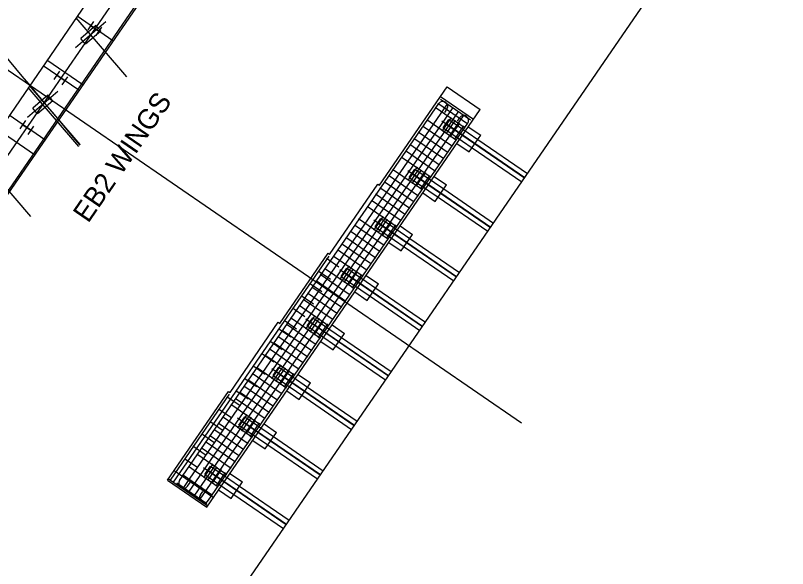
# Model space of a CAD drawing. Extents: x 2378999 to 2381348, y 331302 to 333122.
# Drawn here: x 2379522.9 to 2379599.9, y 331848.3 to 331903.6 of the extents above; entities that cross this region are included whole.
import ezdxf

# ---------------------------------------------------------------- set-up
doc = ezdxf.new("R2010")
doc.units = 0
for name, color, linetype in [('Arrowhead Terminators', 7, 'Continuous'), ('Dimension Lines', 7, 'Continuous'), ('Dimension Lines CELL', 7, 'Continuous'), ('Mis Work Point CELL', 7, 'Continuous'), ('P_SMU_Bent_Cap', 7, 'Continuous'), ('P_SMU_D_Deck_Outline', 7, 'Continuous'), ('P_SMU_Girder_Concrete', 7, 'Continuous'), ('P_SMU_Mis_L_Lines', 7, 'Continuous'), ('P_SMU_Mis_Long_Chord', 7, 'Continuous'), ('P_SMU_Rebar_B_Bar', 7, 'Continuous'), ('P_SMU_Rebar_U_Bar', 7, 'Continuous'), ('Plan Sheet CELL', 7, 'Continuous'), ('Rebar Lines', 7, 'Continuous'), ('Scratch_Level_0', 7, 'Continuous'), ('Sup Concrete Slab Lines', 7, 'Continuous')]:
    doc.layers.add(name, color=color, linetype=linetype)

msp = doc.modelspace()

# ---------------------------------------------------------------- linework, layer by layer
at = {"layer": 'Arrowhead Terminators'}
for p, q in [((2379539.258, 331857.115), (2379565.129, 331894.772)), ((2379539.599, 331856.287), (2379566.025, 331894.75)), ((2379540.148, 331855.909), (2379566.574, 331894.373)), ((2379540.698, 331855.532), (2379567.124, 331893.995)), ((2379565.936, 331894.217), (2379565.7, 331893.874)), ((2379541.247, 331855.154), (2379567.673, 331893.618)), ((2379567.207, 331893.344), (2379566.971, 331893.001)), ((2379542.142, 331855.133), (2379568.014, 331892.79)), ((2379538.663, 331856.93), (2379554.188, 331879.527)), ((2379538.346, 331857.148), (2379544.245, 331865.733)), ((2379540.065, 331856.561), (2379540.301, 331856.904)), ((2379541.335, 331855.688), (2379541.571, 331856.031))]:
    msp.add_line(p, q, dxfattribs=at)
for centre, start, end in [((2379565.533, 331894.494), 325.50932, 145.50932), ((2379567.611, 331893.067), 325.50932, 145.50932), ((2379539.661, 331856.838), 145.50932, 325.50932), ((2379541.739, 331855.41), 145.50932, 325.50932)]:
    msp.add_arc(centre, 0.49, start, end, dxfattribs=at)
at = {"layer": 'Dimension Lines'}
for p, q in [((2379565.04, 331894.789), (2379568.028, 331892.737)), ((2379565.311, 331895.183), (2379568.299, 331893.13)), ((2379564.77, 331894.396), (2379567.758, 331892.343)), ((2379563.921, 331893.159), (2379566.908, 331891.107)), ((2379565.453, 331892.005), (2379566.397, 331893.379)), ((2379565.865, 331891.722), (2379566.809, 331893.096)), ((2379563.496, 331892.541), (2379566.484, 331890.488)), ((2379566.277, 331891.439), (2379567.221, 331892.813)), ((2379566.689, 331891.156), (2379567.633, 331892.53)), ((2379563.071, 331891.923), (2379566.059, 331889.87)), ((2379562.646, 331891.305), (2379565.634, 331889.252)), ((2379561.797, 331890.069), (2379564.785, 331888.016)), ((2379562.222, 331890.687), (2379565.21, 331888.634)), ((2379561.372, 331889.45), (2379564.36, 331887.398)), ((2379562.056, 331887.06), (2379562.999, 331888.434)), ((2379560.523, 331888.214), (2379563.511, 331886.161)), ((2379562.468, 331886.777), (2379563.411, 331888.151)), ((2379562.88, 331886.494), (2379563.824, 331887.867)), ((2379559.674, 331886.978), (2379562.661, 331884.925)), ((2379560.098, 331887.596), (2379563.086, 331885.543)), ((2379563.292, 331886.211), (2379564.236, 331887.584)), ((2379559.249, 331886.36), (2379562.237, 331884.307)), ((2379558.824, 331885.741), (2379561.812, 331883.689)), ((2379558.399, 331885.123), (2379561.387, 331883.071)), ((2379557.975, 331884.505), (2379560.963, 331882.452)), ((2379557.125, 331883.269), (2379560.113, 331881.216)), ((2379558.658, 331882.115), (2379559.602, 331883.488)), ((2379559.07, 331881.832), (2379560.014, 331883.205)), ((2379556.701, 331882.651), (2379559.688, 331880.598)), ((2379559.482, 331881.548), (2379560.426, 331882.922)), ((2379559.894, 331881.265), (2379560.838, 331882.639)), ((2379556.276, 331882.032), (2379559.264, 331879.98)), ((2379555.426, 331880.796), (2379558.414, 331878.743)), ((2379555.851, 331881.414), (2379558.839, 331879.362)), ((2379555.002, 331880.178), (2379557.99, 331878.125)), ((2379554.577, 331879.56), (2379557.565, 331877.507)), ((2379555.26, 331877.169), (2379556.204, 331878.543)), ((2379553.303, 331877.705), (2379556.291, 331875.653)), ((2379553.728, 331878.323), (2379556.715, 331876.271)), ((2379555.672, 331876.886), (2379556.616, 331878.26)), ((2379556.084, 331876.603), (2379557.028, 331877.977)), ((2379556.497, 331876.32), (2379557.44, 331877.694)), ((2379552.878, 331877.087), (2379555.866, 331875.034)), ((2379552.454, 331876.469), (2379555.441, 331874.416)), ((2379552.029, 331875.851), (2379555.017, 331873.798)), ((2379551.179, 331874.614), (2379554.167, 331872.562)), ((2379551.604, 331875.233), (2379554.592, 331873.18)), ((2379550.33, 331873.378), (2379553.318, 331871.325)), ((2379551.863, 331872.224), (2379552.806, 331873.598)), ((2379552.275, 331871.941), (2379553.219, 331873.315)), ((2379552.687, 331871.658), (2379553.631, 331873.032)), ((2379549.905, 331872.76), (2379552.893, 331870.707)), ((2379553.099, 331871.375), (2379554.043, 331872.748)), ((2379549.056, 331871.524), (2379552.044, 331869.471)), ((2379549.481, 331872.142), (2379552.468, 331870.089)), ((2379548.631, 331870.905), (2379551.619, 331868.853)), ((2379548.207, 331870.287), (2379551.194, 331868.235)), ((2379547.782, 331869.669), (2379550.77, 331867.616)), ((2379546.932, 331868.433), (2379549.92, 331866.38)), ((2379548.465, 331867.279), (2379549.409, 331868.652)), ((2379546.508, 331867.815), (2379549.496, 331865.762)), ((2379548.877, 331866.996), (2379549.821, 331868.369)), ((2379549.289, 331866.713), (2379550.233, 331868.086)), ((2379549.701, 331866.429), (2379550.645, 331867.803)), ((2379546.083, 331867.197), (2379549.071, 331865.144)), ((2379545.658, 331866.578), (2379548.646, 331864.526)), ((2379544.809, 331865.342), (2379547.797, 331863.289)), ((2379545.234, 331865.96), (2379548.221, 331863.907)), ((2379544.384, 331864.724), (2379547.372, 331862.671)), ((2379543.535, 331863.488), (2379546.523, 331861.435)), ((2379545.067, 331862.333), (2379546.011, 331863.707)), ((2379545.479, 331862.05), (2379546.423, 331863.424)), ((2379545.892, 331861.767), (2379546.835, 331863.141)), ((2379542.685, 331862.251), (2379545.673, 331860.198)), ((2379543.11, 331862.869), (2379546.098, 331860.817)), ((2379546.304, 331861.484), (2379547.247, 331862.858)), ((2379542.261, 331861.633), (2379545.248, 331859.58)), ((2379541.836, 331861.015), (2379544.824, 331858.962)), ((2379541.411, 331860.397), (2379544.399, 331858.344)), ((2379540.987, 331859.779), (2379543.974, 331857.726)), ((2379540.137, 331858.542), (2379543.125, 331856.489)), ((2379541.67, 331857.388), (2379542.614, 331858.762)), ((2379542.082, 331857.105), (2379543.026, 331858.479)), ((2379539.563, 331857.707), (2379542.551, 331855.654)), ((2379542.494, 331856.822), (2379543.438, 331858.196)), ((2379542.906, 331856.539), (2379543.85, 331857.912)), ((2379538.989, 331856.871), (2379541.977, 331854.819))]:
    msp.add_line(p, q, dxfattribs=at)
at = {"layer": 'Dimension Lines CELL'}
msp.add_line((2379573.397, 331862.836), (2379390.08, 331988.783), dxfattribs=at)
at = {"layer": 'Mis Work Point CELL'}
for p, q in [((2379526.805, 331819.101), (2379599.933, 331925.541)), ((2379512.42, 331875.462), (2379539.034, 331914.2))]:
    msp.add_line(p, q, dxfattribs=at)
at = {"layer": 'P_SMU_Bent_Cap'}
for p, q in [((2379531.913, 331902.921), (2379528.872, 331900.323)), ((2379527.125, 331895.952), (2379524.084, 331893.354))]:
    msp.add_line(p, q, dxfattribs=at)
at = {"layer": 'P_SMU_D_Deck_Outline'}
for p, q in [((2379530.909, 331902.557), (2379529.388, 331901.257)), ((2379531.396, 331901.986), (2379530.909, 331902.557)), ((2379531.396, 331901.986), (2379529.876, 331900.687)), ((2379529.876, 331900.687), (2379529.388, 331901.257)), ((2379526.121, 331895.588), (2379524.601, 331894.289)), ((2379526.609, 331895.018), (2379526.121, 331895.588)), ((2379526.609, 331895.018), (2379525.088, 331893.719)), ((2379525.088, 331893.719), (2379524.601, 331894.289))]:
    msp.add_line(p, q, dxfattribs=at)
at = {"layer": 'P_SMU_Girder_Concrete'}
for p, q in [((2379530.135, 331902.116), (2379530.701, 331902.94)), ((2379530.418, 331902.528), (2379531.229, 331901.971)), ((2379530.945, 331901.559), (2379531.512, 331902.383)), ((2379526.737, 331897.17), (2379527.304, 331897.994)), ((2379527.021, 331897.582), (2379527.831, 331897.026)), ((2379527.548, 331896.613), (2379528.114, 331897.438)), ((2379523.34, 331892.225), (2379523.906, 331893.049)), ((2379565.573, 331892.327), (2379566.139, 331893.151)), ((2379566.139, 331893.151), (2379569.024, 331891.17)), ((2379523.623, 331892.637), (2379524.433, 331892.08)), ((2379524.15, 331891.668), (2379524.716, 331892.492)), ((2379565.573, 331892.327), (2379568.458, 331890.345)), ((2379565.846, 331892.724), (2379573.686, 331887.338)), ((2379565.867, 331892.754), (2379573.707, 331887.368)), ((2379569.024, 331891.17), (2379573.979, 331887.765)), ((2379568.458, 331890.345), (2379573.413, 331886.941)), ((2379562.176, 331887.382), (2379562.742, 331888.206)), ((2379562.448, 331887.779), (2379570.288, 331882.393)), ((2379562.469, 331887.809), (2379570.309, 331882.423)), ((2379562.742, 331888.206), (2379565.627, 331886.224)), ((2379562.176, 331887.382), (2379565.06, 331885.4)), ((2379565.627, 331886.224), (2379570.582, 331882.82)), ((2379565.06, 331885.4), (2379570.016, 331881.996)), ((2379558.778, 331882.437), (2379559.344, 331883.261)), ((2379559.344, 331883.261), (2379562.229, 331881.279)), ((2379558.778, 331882.437), (2379561.663, 331880.455)), ((2379559.051, 331882.834), (2379566.891, 331877.447)), ((2379559.071, 331882.864), (2379566.911, 331877.477)), ((2379562.229, 331881.279), (2379567.184, 331877.874)), ((2379561.663, 331880.455), (2379566.618, 331877.05)), ((2379555.38, 331877.491), (2379555.947, 331878.316)), ((2379555.653, 331877.889), (2379563.493, 331872.502)), ((2379555.674, 331877.918), (2379563.514, 331872.532)), ((2379555.947, 331878.316), (2379558.831, 331876.334)), ((2379555.38, 331877.491), (2379558.265, 331875.509)), ((2379558.831, 331876.334), (2379563.787, 331872.929)), ((2379558.265, 331875.509), (2379563.22, 331872.105)), ((2379551.983, 331872.546), (2379552.549, 331873.37)), ((2379552.549, 331873.37), (2379555.434, 331871.388)), ((2379551.983, 331872.546), (2379554.867, 331870.564)), ((2379552.256, 331872.943), (2379560.096, 331867.557)), ((2379552.276, 331872.973), (2379560.116, 331867.587)), ((2379555.434, 331871.388), (2379560.389, 331867.984)), ((2379554.867, 331870.564), (2379559.823, 331867.16)), ((2379548.585, 331867.601), (2379549.151, 331868.425)), ((2379549.151, 331868.425), (2379552.036, 331866.443)), ((2379548.858, 331867.998), (2379556.698, 331862.612)), ((2379548.878, 331868.028), (2379556.718, 331862.641)), ((2379548.585, 331867.601), (2379551.47, 331865.619)), ((2379552.036, 331866.443), (2379556.991, 331863.039)), ((2379551.47, 331865.619), (2379556.425, 331862.214)), ((2379545.187, 331862.655), (2379545.754, 331863.48)), ((2379545.46, 331863.053), (2379553.3, 331857.666)), ((2379545.481, 331863.082), (2379553.321, 331857.696)), ((2379545.754, 331863.48), (2379548.638, 331861.498)), ((2379545.187, 331862.655), (2379548.072, 331860.673)), ((2379548.638, 331861.498), (2379553.594, 331858.093)), ((2379548.072, 331860.673), (2379553.027, 331857.269)), ((2379541.79, 331857.71), (2379542.356, 331858.534)), ((2379542.356, 331858.534), (2379545.241, 331856.552)), ((2379541.79, 331857.71), (2379544.675, 331855.728)), ((2379542.063, 331858.107), (2379549.903, 331852.721)), ((2379542.083, 331858.137), (2379549.923, 331852.751)), ((2379545.241, 331856.552), (2379550.196, 331853.148)), ((2379544.675, 331855.728), (2379549.63, 331852.324))]:
    msp.add_line(p, q, dxfattribs=at)
at = {"layer": 'P_SMU_Mis_L_Lines'}
for p, q in [((2379533.98, 331897.423), (2379528.935, 331903.327)), ((2379529.192, 331890.454), (2379524.148, 331896.359)), ((2379524.404, 331883.486), (2379519.36, 331889.39))]:
    msp.add_line(p, q, dxfattribs=at)
at = {"layer": 'P_SMU_Mis_Long_Chord'}
msp.add_arc((2384957.239, 336436.342), 7080, 219.8160166, 219.9451668, dxfattribs=at)
at = {"layer": 'P_SMU_Rebar_B_Bar'}
for p, q in [((2379536.991, 331915.053), (2379511.549, 331878.021)), ((2379540.491, 331912.495), (2379513.877, 331873.757)), ((2379529.591, 331896.629), (2379526.019, 331899.083)), ((2379559.207, 331886.594), (2379565.952, 331896.411)), ((2379565.952, 331896.411), (2379569.249, 331894.146)), ((2379565.295, 331895.454), (2379568.592, 331893.189)), ((2379541.977, 331854.451), (2379569.249, 331894.146)), ((2379568.071, 331892.431), (2379569.307, 331891.582)), ((2379524.777, 331889.623), (2379521.206, 331892.077)), ((2379568.175, 331889.933), (2379569.307, 331891.582)), ((2379566.939, 331890.783), (2379568.175, 331889.933)), ((2379564.673, 331887.486), (2379565.91, 331886.636)), ((2379554.235, 331879.697), (2379559.048, 331886.703)), ((2379559.048, 331886.703), (2379559.207, 331886.594)), ((2379564.777, 331884.988), (2379565.91, 331886.636)), ((2379563.541, 331885.837), (2379564.777, 331884.988)), ((2379561.276, 331882.54), (2379562.512, 331881.691)), ((2379561.38, 331880.043), (2379562.512, 331881.691)), ((2379560.143, 331880.892), (2379561.38, 331880.043)), ((2379549.263, 331872.8), (2379554.077, 331879.806)), ((2379554.077, 331879.806), (2379554.235, 331879.697)), ((2379557.878, 331877.595), (2379559.114, 331876.746)), ((2379557.982, 331875.097), (2379559.114, 331876.746)), ((2379556.746, 331875.947), (2379557.982, 331875.097)), ((2379544.291, 331865.903), (2379549.104, 331872.909)), ((2379549.104, 331872.909), (2379549.263, 331872.8)), ((2379554.481, 331872.65), (2379555.717, 331871.8)), ((2379554.584, 331870.152), (2379555.717, 331871.8)), ((2379553.348, 331871.001), (2379554.584, 331870.152)), ((2379551.083, 331867.705), (2379552.319, 331866.855)), ((2379551.187, 331865.207), (2379552.319, 331866.855)), ((2379538.045, 331857.152), (2379544.133, 331866.012)), ((2379544.133, 331866.012), (2379544.291, 331865.903)), ((2379549.95, 331866.056), (2379551.187, 331865.207)), ((2379547.685, 331862.759), (2379548.922, 331861.91)), ((2379547.789, 331860.261), (2379548.922, 331861.91)), ((2379546.553, 331861.111), (2379547.789, 331860.261)), ((2379538.703, 331858.109), (2379542.634, 331855.408)), ((2379544.288, 331857.814), (2379545.524, 331856.964)), ((2379538.045, 331857.152), (2379541.977, 331854.451)), ((2379544.391, 331855.316), (2379545.524, 331856.964)), ((2379543.155, 331856.165), (2379544.391, 331855.316))]:
    msp.add_line(p, q, dxfattribs=at)
at = {"layer": 'P_SMU_Rebar_U_Bar'}
for p, q in [((2379553.931, 331879.299), (2379555.167, 331878.45)), ((2379553.082, 331878.063), (2379554.318, 331877.214)), ((2379552.232, 331876.827), (2379553.469, 331875.977)), ((2379551.383, 331875.59), (2379552.619, 331874.741)), ((2379550.533, 331874.354), (2379551.77, 331873.505)), ((2379549.684, 331873.118), (2379550.92, 331872.268)), ((2379549.118, 331872.293), (2379550.354, 331871.444)), ((2379548.268, 331871.057), (2379549.505, 331870.208)), ((2379547.419, 331869.821), (2379548.655, 331868.971)), ((2379546.569, 331868.584), (2379547.806, 331867.735)), ((2379545.72, 331867.348), (2379546.956, 331866.499)), ((2379544.871, 331866.112), (2379546.107, 331865.262)), ((2379543.984, 331865.508), (2379545.22, 331864.658)), ((2379543.134, 331864.272), (2379544.371, 331863.422)), ((2379542.285, 331863.035), (2379543.521, 331862.186)), ((2379541.436, 331861.799), (2379542.672, 331860.949)), ((2379540.586, 331860.563), (2379541.822, 331859.713)), ((2379539.737, 331859.326), (2379540.973, 331858.477))]:
    msp.add_line(p, q, dxfattribs=at)
at = {"layer": 'Plan Sheet CELL'}
msp.add_line((2379529.339, 331890.668), (2379524.294, 331896.572), dxfattribs=at)
at = {"layer": 'Rebar Lines'}
for p, q in [((2379532.609, 331901.022), (2379529.038, 331903.476)), ((2379529.212, 331896.077), (2379525.64, 331898.531)), ((2379525.814, 331891.132), (2379522.242, 331893.586)), ((2379565.437, 331893.027), (2379573.696, 331887.353)), ((2379562.039, 331888.082), (2379570.299, 331882.408)), ((2379558.642, 331883.137), (2379566.901, 331877.462)), ((2379555.244, 331878.192), (2379563.503, 331872.517)), ((2379551.846, 331873.246), (2379560.106, 331867.572)), ((2379548.449, 331868.301), (2379556.708, 331862.626)), ((2379545.051, 331863.356), (2379553.311, 331857.681)), ((2379541.654, 331858.41), (2379549.913, 331852.736))]:
    msp.add_line(p, q, dxfattribs=at)
at = {"layer": 'Scratch_Level_0'}
for p, q in [((2379540.354, 331912.589), (2379513.739, 331873.851)), ((2379538.14, 331857.289), (2379542.071, 331854.588))]:
    msp.add_line(p, q, dxfattribs=at)

# ---------------------------------------------------------------- texts
at = {"layer": 'Sup Concrete Slab Lines'}
msp.add_text('EB2 WINGS', height=2, rotation=55.50932, dxfattribs=at).set_placement((2379530.139, 331882.74))

doc.saveas('drawing.dxf')
